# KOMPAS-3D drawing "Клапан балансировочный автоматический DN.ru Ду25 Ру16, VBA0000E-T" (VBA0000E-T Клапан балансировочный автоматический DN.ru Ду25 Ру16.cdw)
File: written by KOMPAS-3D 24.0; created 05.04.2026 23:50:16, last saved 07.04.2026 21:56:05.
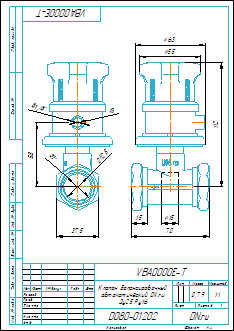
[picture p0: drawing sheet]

Document properties: Автор: tyuri; Форматы листов документа: A4; Полное имя файла: VBA0000E-T Клапан балансировочный автоматический DN.ru Ду25 Ру16.m3d; Масса: 0.788; Наименование: Клапан балансировочный автоматический DN.ru Ду25 Ру16; Количество листов документа: 1; Примечание: D080-01202

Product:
- Body: Тело 6  | qty 1
    Масса: 1.195907
- Part/product: Клапан балансировочный автоматический DN.ru Ду25 Ру16  | designation VBA0000E-T
    Масса: 0.788
    Раздел спецификации: Прочие изделия
    Примечание: D080-01202

Views: Вид 1, Сзади, Проекционный вид 2
Referenced files in D:\Аутсорс\Клапан балансировочный автоматический DN.ru VBA0000E-T Ду15 Ру16\DN15\: Клапан балансировочный автоматический DN.ru Ду15 Ру16.m3d, VBA0000E-T - Клапан балансировочный автоматический DN.ru Ду15 Ру16.cdw
Referenced files in D:\Аутсорс\VBA0000E-T Клапан балансировочный автоматический DN.ru\DN25\: VBA0000E-T Клапан балансировочный автоматический DN.ru Ду25 Ру16.m3d
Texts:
  VBA0000E-T
  Клапан балансировочный
  автоматический DN.ru
  Ду25 Ру16
  Клапан балансировочный автоматический DN.ru Ду25 Ру16
  VBA0000E-T Клапан балансировочный автоматический DN.ru Ду25 Ру16
Dimensions and other numbers on the sheet: 0; 3; 2; 4; 37,5; 58; 25; 15; 70; 112; 63; 55; 1:1; 1; 0,79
